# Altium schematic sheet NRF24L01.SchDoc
size A; SheetNumber: 3; SheetTotal: 4
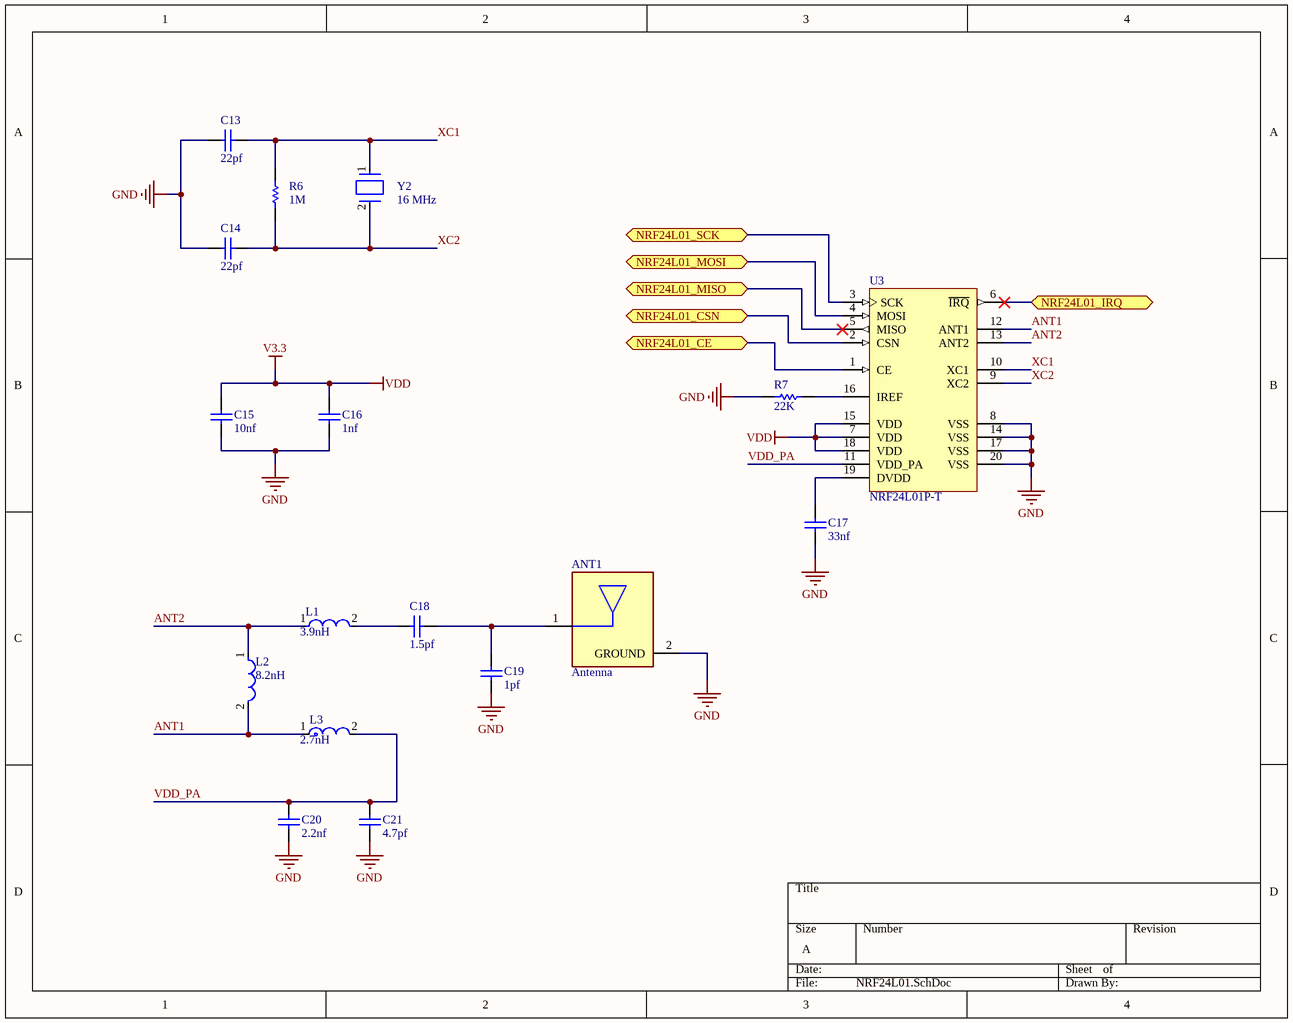
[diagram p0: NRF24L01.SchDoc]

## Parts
ANT1  Antenna  [FP-211964-0001-MFG]
C13  value 22pf  [CAPC1206(3216)190_N]  (hidden comment: CAP 1206)
C14  value 22pf  [CAPC1206(3216)190_N]  (hidden comment: CAP 1206)
C15  value 10nf  [CAPC1206(3216)190_N]  (hidden comment: CAP 1206)
C16  value 1nf  [CAPC1206(3216)190_N]  (hidden comment: CAP 1206)
C17  value 33nf  [CAPC1206(3216)190_N]  (hidden comment: CAP 1206)
C18  value 1.5pf  [CAPC1206(3216)190_N]  (hidden comment: CAP 1206)
C19  value 1pf  [CAPC1206(3216)190_N]  (hidden comment: CAP 1206)
C20  value 2.2nf  [CAPC1206(3216)190_N]  (hidden comment: CAP 1206)
C21  value 4.7pf  [CAPC1206(3216)190_N]  (hidden comment: CAP 1206)
L1  Inductance: 3.9nH  [FP-LQM21DN_00-IPC_B]  (hidden comment: LQM21NNR15K10D)
L2  Inductance: 8.2nH  [FP-LQM21DN_00-IPC_B]  (hidden comment: LQM21NNR15K10D)
L3  Inductance: 2.7nH  [FP-LQG18HH_00-IPC_A]  (hidden comment: LQG18HN2N2S00D)
R6  value 1M  [RESC3216X70X50NL05T20]  (hidden comment: ERJ-8GEY0R00V)
R7  value 22K  [RESC3216X70X50NL05T20]  (hidden comment: ERJ-8GEY0R00V)
U3  NRF24L01P-T  [NRSC-QFN-20_L]
Y2  Operating Frequency: 16 MHz  [FP-ABLS-MFG]  (hidden comment: ABLS-8.000MHZ-B2-T)

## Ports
NRF24L01_CE (bidir, see Microcontroller[4A]), NRF24L01_CSN (bidir, see Microcontroller[4A]), NRF24L01_IRQ (bidir, see Microcontroller[4B]), NRF24L01_MISO (bidir, see Microcontroller[4A]), NRF24L01_MOSI (bidir, see Microcontroller[4A]), NRF24L01_SCK (bidir, see Microcontroller[4A])

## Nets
GND: ANT1.2(GROUND) C13.2 C14.2 C15.2 C16.2 C17.2 C19.1 C20.1 C21.1 R7.2 U3.8(VSS) U3.14(VSS) U3.17(VSS) U3.20(VSS)
V3.3: C15.1 C16.1 U3.7(VDD) U3.15(VDD) U3.18(VDD)  [also labelled VDD]
ANT1: L2.2 L3.1 U3.12(ANT1)
ANT2: L1.1 L2.1 U3.13(ANT2)
NRF24L01_CE: U3.1(CE) ; port NRF24L01_CE
NRF24L01_CSN: U3.2(CSN) ; port NRF24L01_CSN
NRF24L01_IRQ: U3.6(~{IRQ}) ; port NRF24L01_IRQ
NRF24L01_MISO: U3.5(MISO) ; port NRF24L01_MISO
NRF24L01_MOSI: U3.4(MOSI) ; port NRF24L01_MOSI
NRF24L01_SCK: U3.3(SCK) ; port NRF24L01_SCK
VDD_PA: C20.2 C21.2 L3.2 U3.11(VDD_PA)
XC1: C13.1 R6.2 U3.10(XC1) Y2.1
XC2: C14.1 R6.1 U3.9(XC2) Y2.2
NetANT1_1: ANT1.1(FEED) C18.2 C19.2
NetC17_1: C17.1 U3.19(DVDD)
NetC18_1: C18.1 L1.2
NetR7_1: R7.1 U3.16(IREF)

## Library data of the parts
ANT1 = CMP-04721-000010-1: 2.4/5GHZ LTCC ANT 3.2X1.6MM
C13-C21 = CMP-1037-04961-1: Tolerance: Â±10%; Case-EIA: 1206; Case-Metric: 3216; Rated Voltage: 6.3 V
L1 L2 = CMP-06042-016815-1: Multilayer Type Inductor for General Circuits, 0805 (2012), 0.15μH, 10%, 0.32Ω, 250mA; DC Resistance (DCR): 320mR; Test Frequency: 25MHz; Shielding: Shielded; Q Factor: 20; Self Resonant Frequency: 270MHz; Core Material: Ferrite
L3 = CMP-06042-006288-1: Multilayer type RF Inductor 2.2nH ±0.3nH 0.1Ω 1100mA 0603; Max DC Current: 500mA; Core Material: Air; Self Resonant Frequency: 6GHz; Q Factor: 12; DC Resistance (DCR): 100mR; Shielding: Unshielded; Test Frequency: 100MHz
R6 R7 = CMP-2003-00541-1: Manufacturer: Panasonic
U3 = CMP-2000-06859-1: Single Chip Transceiver, 2.4 GHz, 60 mW, 1.9 to 3.6 V, -40 to 85 degC, 20-Pin QFN, RoHS, Tray; Manufacturer: Nordic Semiconductor; Data Rate (Max): 2Mbps; Current - Transmitting: 7mA~11.3mA; Power - Output: 0dBm; Other Names: 1490-1019; Online Catalog: nRF24L01+; Current - Receiving: 12.6mA~13.5mA; For Use With: 1490-1002-ND-KITEVALUATIONNRF24L01P1568-1295-ND-SPARKFUNTRANSCEIVERBREAKOUT-1568-1296-ND-SPARKFUNTRANSCEIVERBREAKOUT-1471-1410-ND-DEVBOARDNRFSCLICKNRF24L01P-MODULE-PCB-ND-KITEVALNRF24L01+PCBANTENNANRF24L01P-MODULE-SMA-ND-KITEVALNRF24L01+SMACONNNRF24L01P-UPGRADE-ND-UPGRADE2PCB/1SMANRF24L01103990038-ND-DEVDUINOSENSORNODEV1.3103990053-ND-DEVDUINOSENSORNODEV2(ATMEGA103990074-ND-DEVDUINOSENSORNODE106990026-ND-ENERGYMONITORSHIELDV2113990088-ND-WIRELESSGATESHIELD113990095-ND-DEVDUINOSENSORNODEV3(ATMEGA106030001-ND-ENERGYMONITORSHIELD1597-1361-ND-DEVDUINOSENSORNODEV2.2(ATMEG105990030-ND-RGBWSTRIPWIRELESSSHIELDV1.0; Frequency: 2.4GHz; Design Resources: DevelopmentToolSelector; RF Family/Standard: GeneralISM>1GHZ; Serial Interfaces: SPI; Sensitivity: -94dBm; Voltage - Supply: 1.9V~3.6V; Modulation: GFSK
Y2 = CMP-27762-009874-1: CRYSTAL 8.0000MHZ 18PF SMD; ESR (Equivalent Series Resistance): 80R; Frequency Stability: 50ppm; Tolerance: 20ppm; Frequency: 8MHz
